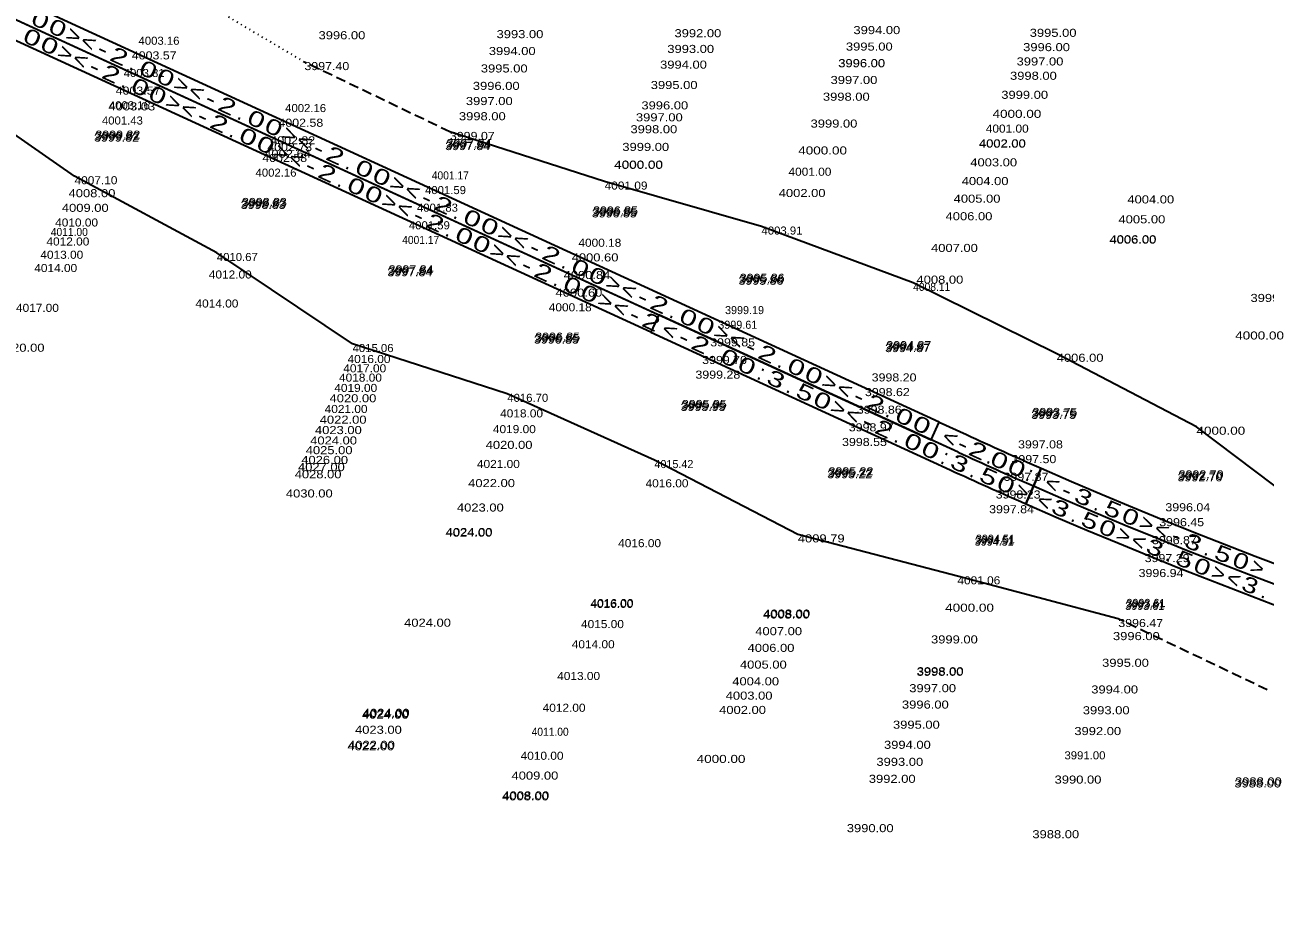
# Model space of a CAD drawing. Extents: x 49942 to 56479, y 47140 to 53283.
# Drawn here: x 50522 to 51291, y 49746 to 50295 of the extents above; entities that cross this region are included whole.
import ezdxf
from ezdxf.enums import TextEntityAlignment as Align

# ---------------------------------------------------------------- set-up
doc = ezdxf.new("R2010")
doc.units = 0
doc.header["$LTSCALE"] = 2
doc.linetypes.add('DOTTED', pattern=[1.5, 0.3, -1.2])
doc.linetypes.add('MEDIUM_DASHED', pattern=[4.5, 3, -1.5])
doc.layers.add('29', color=7, linetype='Continuous')
doc.layers.add('59', color=7, linetype='Continuous', lineweight=35)
doc.layers.add('63', color=7, linetype='Continuous', lineweight=35)

msp = doc.modelspace()

# ---------------------------------------------------------------- linework, layer by layer
at = {"layer": '59', "linetype": 'DOTTED'}
msp.add_line((50695.507, 50271.844), (50609.015, 50323.127), dxfattribs=at)
at = {"layer": '59', "linetype": 'MEDIUM_DASHED'}
for p, q in [((50785.68, 50228.581), (50695.507, 50271.844)), ((51292.327, 49882.958), (51199.974, 49926.861))]:
    msp.add_line(p, q, dxfattribs=at)
at = {"layer": '59'}
for p, q in [((50553.024, 50201.131), (50469.673, 50259.257)), ((50881.594, 50197.827), (50785.68, 50228.581)), ((50641.234, 50153.59), (50553.024, 50201.131)), ((50978.838, 50169.97), (50881.594, 50197.827)), ((51072.858, 50135.088), (50978.838, 50169.97)), ((50725.383, 50097.199), (50641.234, 50153.59)), ((51161.816, 50091.173), (51072.858, 50135.088)), ((50821.258, 50066.361), (50725.383, 50097.199)), ((51248.45, 50045.982), (51161.816, 50091.173)), ((50912.456, 50025.33), (50821.258, 50066.361)), ((51329.711, 49984.424), (51248.45, 50045.982)), ((51001.352, 49979.284), (50912.456, 50025.33)), ((51100.256, 49953.31), (51001.352, 49979.284)), ((51199.974, 49926.861), (51100.256, 49953.31))]:
    msp.add_line(p, q, dxfattribs=at)
at = {"layer": '63'}
for p, q in [((50910.165, 50104.44), (51095.828, 50019.23)), ((51088.959, 50048.79), (51105.839, 50041.043)), ((51152.244, 50020.223), (51147.426, 50009.233)), ((51147.426, 50009.233), (51152.244, 50020.223)), ((51142.608, 49998.243), (51147.426, 50009.233)), ((51147.426, 50009.233), (51142.608, 49998.243))]:
    msp.add_line(p, q, dxfattribs=at)
for points in [[(51088.959, 50048.79), (49952.321, 50570.45), (49947.316, 50559.544), (51083.954, 50037.883)], [(50910.165, 50104.44), (49942.31, 50548.638), (49947.316, 50559.544), (50915.171, 50115.346)]]:
    msp.add_lwpolyline(points, close=True, dxfattribs=at)
for points in [[(51100.834, 50030.136), (50915.171, 50115.346), (50910.165, 50104.44)], [(51100.834, 50030.136), (51083.954, 50037.883), (51088.959, 50048.79)]]:
    msp.add_lwpolyline(points, dxfattribs=at)
for radius, start, end in [(2975.18, 245.34722, 246.32672), (2987.18, 245.34722, 246.32672), (2987.18, 245.34722, 246.32672), (2975.18, 246.32672, 271.49967), (2999.18, 245.34722, 246.32672), (2987.18, 246.32672, 271.49967), (2987.18, 246.32672, 271.49967), (2999.18, 246.32672, 271.49967)]:
    msp.add_arc((52346.841, 52745.042), radius, start, end, dxfattribs=at)

# ---------------------------------------------------------------- texts
at = {"layer": '29'}
for s, width, p in [('3996.00', 1.2, (50704.276, 50285.95)), ('3993.00', 1.2, (50814.621, 50286.64)), ('3992.00', 1.2, (50924.913, 50287.213)), ('3994.00', 1.2, (51035.83, 50289.147)), ('3995.00', 1.2, (51145.084, 50287.459)), ('4003.16', 1.05, (50592.689, 50282.556)), ('3993.00', 1.2, (50920.447, 50277.481)), ('3995.00', 1.2, (51031.146, 50278.942)), ('3996.00', 1.2, (51141.013, 50278.59)), ('4003.57', 1.15, (50588.518, 50273.467)), ('3994.00', 1.2, (50809.818, 50276.175)), ('3997.00', 1.2, (51136.943, 50269.721)), ('4003.81', 1.05, (50583.512, 50262.561)), ('3997.40', 1.15, (50695.507, 50266.844)), ('3995.00', 1.2, (50804.865, 50265.383)), ('3994.00', 1.2, (50915.98, 50267.75)), ('3996.00', 1.2, (51026.397, 50268.594)), ('3996.00', 1.2, (51026.423, 50268.651)), ('3996.00', 1.2, (51026.449, 50268.708)), ('3996.00', 1.2, (50799.912, 50254.591)), ('3995.00', 1.2, (50910.187, 50255.126)), ('3997.00', 1.2, (51021.643, 50258.237)), ('3998.00', 1.2, (51132.872, 50260.852)), ('4003.57', 1.15, (50578.507, 50251.655)), ('3998.00', 1.2, (51016.89, 50247.88)), ('3999.00', 1.2, (51127.459, 50249.057)), ('4003.03', 1.2, (50574.021, 50241.88)), ('4003.16', 1.05, (50574.336, 50242.566)), ('4002.16', 1.05, (50683.574, 50240.844)), ('3997.00', 1.2, (50795.6, 50245.195)), ('3996.00', 1.2, (50904.393, 50242.503)), ('4001.43', 1.05, (50570.007, 50233.134)), ('4002.58', 1.15, (50679.403, 50231.755)), ('3998.00', 1.2, (50791.281, 50235.785)), ('3997.00', 1.2, (50901.003, 50235.115)), ('3999.00', 1.2, (51009.25, 50231.234)), ('4000.00', 1.25, (51122.046, 50237.262)), ('3999.82', 1.15, (50565.576, 50223.48)), ('3999.82', 1.15, (50565.994, 50224.389)), ('3999.07', 1.15, (50785.68, 50223.581)), ('3998.00', 1.2, (50897.612, 50227.728)), ('4001.00', 1.1, (51117.856, 50228.132)), ('3999.82', 1.15, (50565.159, 50222.571)), ('4002.73', 1.15, (50672.487, 50216.685)), ('4002.82', 1.15, (50674.398, 50220.849)), ('3997.84', 1.15, (50782.802, 50217.309)), ('3997.84', 1.15, (50783.219, 50218.218)), ('3997.84', 1.15, (50783.636, 50219.127)), ('3999.00', 1.2, (50892.588, 50216.78)), ('4002.00', 1.2, (51113.576, 50218.808)), ('4002.00', 1.2, (51113.622, 50218.907)), ('4002.00', 1.2, (51113.666, 50219.002)), ('4002.58', 1.15, (50669.392, 50209.943)), ('4002.64', 1.2, (50670.576, 50212.522)), ('4000.00', 1.25, (51001.611, 50214.588)), ('4002.16', 1.05, (50665.221, 50200.854)), ('4000.00', 1.25, (50887.482, 50205.656)), ('4000.00', 1.25, (50887.523, 50205.744)), ('4000.00', 1.25, (50887.563, 50205.832)), ('4001.00', 1.1, (50995.562, 50201.409)), ('4003.00', 1.2, (51108.255, 50207.214)), ('4007.10', 1.1, (50553.024, 50196.131)), ('4001.17', 0.95, (50774.46, 50199.132)), ('4001.09', 1.1, (50881.594, 50192.827)), ('4004.00', 1.2, (51102.934, 50195.62)), ('4008.00', 1.2, (50549.343, 50188.111)), ('4001.59', 1.05, (50770.288, 50190.044)), ('4002.00', 1.2, (50989.514, 50188.23)), ('4005.00', 1.2, (51097.936, 50184.729)), ('4004.00', 1.2, (51205.618, 50184.267)), ('4009.00', 1.2, (50545.179, 50179.036)), ('3998.83', 1.15, (50656.044, 50180.86)), ('3998.83', 1.15, (50656.462, 50181.768)), ('3998.83', 1.15, (50656.879, 50182.677)), ('4001.83', 1.05, (50765.283, 50179.137)), ('3996.85', 1.15, (50874.521, 50177.415)), ('4010.00', 1.1, (50541.014, 50169.962)), ('3996.85', 1.15, (50873.687, 50175.597)), ('3996.85', 1.15, (50874.104, 50176.506)), ('4006.00', 1.2, (51092.937, 50173.837)), ('4005.00', 1.2, (51200.108, 50171.928)), ('4011.00', 0.95, (50538.314, 50164.079)), ('4001.59', 1.05, (50760.278, 50168.231)), ('4003.91', 1.05, (50978.838, 50164.97)), ('4012.00', 1.1, (50535.614, 50158.195)), ('4001.17', 0.95, (50756.106, 50159.143)), ('4000.18', 1.1, (50865.345, 50157.42)), ('4007.00', 1.2, (51083.925, 50154.2)), ('4006.00', 1.2, (51194.48, 50159.324)), ('4006.00', 1.2, (51194.552, 50159.485)), ('4006.00', 1.2, (51194.597, 50159.588)), ('4013.00', 1.1, (50531.843, 50149.979)), ('4010.67', 1.05, (50641.234, 50148.59)), ('4000.60', 1.2, (50861.173, 50148.332)), ('4014.00', 1.1, (50528.072, 50141.763)), ('3997.84', 1.15, (50746.93, 50139.148)), ('3997.84', 1.15, (50747.347, 50140.057)), ('3997.84', 1.15, (50747.764, 50140.966)), ('4012.00', 1.1, (50636.259, 50137.75)), ('4000.84', 1.2, (50856.168, 50137.426)), ('3995.86', 1.15, (50964.572, 50133.885)), ('3995.86', 1.15, (50964.989, 50134.794)), ('3995.86', 1.15, (50965.407, 50135.703)), ('4008.00', 1.2, (51074.912, 50134.563)), ('4000.60', 1.2, (50851.163, 50126.519)), ('4008.11', 0.95, (51072.858, 50130.088)), ('3999.00', 1.2, (51281.921, 50123.228)), ('4017.00', 1.1, (50516.743, 50117.077)), ('4014.00', 1.1, (50628.01, 50119.776)), ('4000.18', 1.1, (50846.991, 50117.431)), ('4000.00', 1.25, (51272.46, 50099.981)), ('4020.00', 1.2, (50505.413, 50092.391)), ('4015.06', 1.05, (50725.383, 50092.2)), ('3996.85', 1.15, (50837.815, 50097.436)), ('3996.85', 1.15, (50838.232, 50098.345)), ('3996.85', 1.15, (50838.649, 50099.254)), ('3999.85', 1.15, (50947.053, 50095.714)), ('3994.87', 1.15, (51055.457, 50092.174)), ('3994.87', 1.15, (51055.875, 50093.083)), ('3994.87', 1.15, (51056.292, 50093.991)), ('4016.00', 1.1, (50722.263, 50085.401)), ('3999.70', 1.15, (50942.048, 50084.808)), ('4006.00', 1.2, (51161.816, 50086.173)), ('4017.00', 1.1, (50719.617, 50079.637)), ('4018.00', 1.1, (50716.971, 50073.872)), ('3999.28', 1.15, (50937.877, 50075.719)), ('3998.20', 1.15, (51047.115, 50073.997)), ('4019.00', 1.1, (50714.037, 50067.479)), ('4016.70', 1.05, (50821.258, 50061.361)), ('3998.62', 1.15, (51042.944, 50064.908)), ('4021.00', 1.1, (50708.059, 50054.453)), ('4020.00', 1.2, (50711.103, 50061.085)), ('3995.95', 1.15, (50928.7, 50055.724)), ('3995.95', 1.15, (50929.117, 50056.633)), ('3995.95', 1.15, (50929.534, 50057.542)), ('3998.86', 1.15, (51037.938, 50054.002)), ('4022.00', 1.2, (50705.015, 50047.821)), ('4018.00', 1.1, (50816.83, 50051.713)), ('3993.75', 1.15, (51146.014, 50050.785)), ('3993.75', 1.15, (51146.422, 50051.698)), ('3993.75', 1.15, (51146.829, 50052.611)), ('4023.00', 1.2, (50702.062, 50041.387)), ('4019.00', 1.1, (50812.355, 50041.961)), ('3998.97', 1.15, (51032.933, 50043.096)), ('4000.00', 1.25, (51248.45, 50040.982)), ('4024.00', 1.2, (50699.109, 50034.953)), ('4020.00', 1.2, (50807.879, 50032.21)), ('3998.55', 1.15, (51028.762, 50034.007)), ('3997.08', 1.15, (51137.859, 50032.523)), ('4026.00', 1.2, (50693.569, 50022.881)), ('4025.00', 1.2, (50696.339, 50028.917)), ('3997.50', 1.15, (51133.782, 50023.392)), ('4027.00', 1.2, (50691.531, 50018.441)), ('4021.00', 1.1, (50802.449, 50020.378)), ('3995.22', 1.15, (51020.42, 50015.83)), ('4028.00', 1.2, (50689.493, 50014.001)), ('4022.00', 1.2, (50797.019, 50008.547)), ('4016.00', 1.1, (50906.983, 50008.405)), ('3995.22', 1.15, (51019.585, 50014.012)), ('3995.22', 1.15, (51020.002, 50014.921)), ('3997.87', 1.15, (51128.889, 50012.435)), ('3992.70', 1.15, (51236.697, 50012.1)), ('3992.70', 1.15, (51237.074, 50013.026)), ('3992.70', 1.15, (51237.45, 50013.952)), ('4030.00', 1.2, (50684.041, 50002.12)), ('3998.23', 1.15, (51123.997, 50001.477)), ('4023.00', 1.2, (50790.065, 49993.394)), ('3997.84', 1.15, (51119.919, 49992.346)), ('3996.04', 1.15, (51229.158, 49993.575)), ('4024.00', 1.2, (50782.932, 49977.853)), ('4024.00', 1.2, (50783.021, 49978.048)), ('4024.00', 1.2, (50783.111, 49978.242)), ('3996.45', 1.15, (51225.389, 49984.313)), ('4016.00', 1.1, (50889.971, 49971.339)), ('4009.79', 1.2, (51001.352, 49974.284)), ('3996.87', 1.15, (51220.865, 49973.198)), ('3997.29', 1.15, (51216.342, 49962.083)), ('4001.06', 1.1, (51100.256, 49948.31)), ('3996.94', 1.15, (51212.573, 49952.821)), ('4016.00', 1.1, (50872.697, 49933.7)), ('4016.00', 1.1, (50872.814, 49933.956)), ('4016.00', 1.1, (50872.932, 49934.211)), ('4000.00', 1.25, (51092.688, 49931.362)), ('4008.00', 1.2, (50979.708, 49927.124)), ('4008.00', 1.2, (50979.843, 49927.419)), ('4008.00', 1.2, (50979.979, 49927.714)), ('4024.00', 1.2, (50757.323, 49922.053)), ('4015.00', 1.1, (50866.963, 49921.207)), ('4007.00', 1.2, (50974.965, 49916.791)), ('3996.47', 1.15, (51199.974, 49921.862)), ('4014.00', 1.1, (50861.229, 49908.713)), ('3999.00', 1.2, (51083.908, 49911.698)), ('3996.00', 1.2, (51196.677, 49913.761)), ('4006.00', 1.2, (50970.223, 49906.458)), ('4005.00', 1.2, (50965.471, 49896.104)), ('3995.00', 1.2, (51189.95, 49897.231)), ('4013.00', 1.1, (50852.201, 49889.041)), ('4004.00', 1.2, (50960.72, 49885.751)), ('3998.00', 1.2, (51074.957, 49891.652)), ('3998.00', 1.2, (51075.034, 49891.824)), ('3998.00', 1.2, (51075.111, 49891.996)), ('4003.00', 1.2, (50956.65, 49876.883)), ('3997.00', 1.2, (51070.422, 49881.497)), ('3994.00', 1.2, (51183.224, 49880.701)), ('4012.00', 1.1, (50843.172, 49869.369)), ('3996.00', 1.2, (51065.888, 49871.342)), ('4024.00', 1.2, (50731.175, 49865.079)), ('4024.00', 1.2, (50731.444, 49865.666)), ('4024.00', 1.2, (50731.714, 49866.253)), ('4002.00', 1.2, (50952.58, 49868.016)), ('3993.00', 1.2, (51177.981, 49867.818)), ('4023.00', 1.2, (50726.887, 49855.737)), ('4011.00', 0.95, (50836.351, 49854.507)), ('3995.00', 1.2, (51060.325, 49858.885)), ('3992.00', 1.2, (51172.738, 49854.935)), ('4022.00', 1.2, (50722.599, 49846.393)), ('3994.00', 1.2, (51054.763, 49846.427)), ('4022.00', 1.2, (50722.188, 49845.499)), ('4010.00', 1.1, (50829.531, 49839.646)), ('3991.00', 1.05, (51166.624, 49839.911)), ('4000.00', 1.25, (50938.656, 49837.678)), ('3993.00', 1.2, (51050.056, 49835.886)), ('4009.00', 1.2, (50823.892, 49827.36)), ('3992.00', 1.2, (51045.348, 49825.344)), ('3990.00', 1.2, (51160.509, 49824.886)), ('3988.00', 1.2, (51272.345, 49823.726)), ('3988.00', 1.2, (51271.892, 49822.495)), ('4008.00', 1.2, (50817.982, 49814.482)), ('4008.00', 1.2, (50818.253, 49815.074)), ('3990.00', 1.2, (51031.709, 49794.798)), ('3988.00', 1.2, (51146.733, 49791.033))]:
    msp.add_text(s, height=5, dxfattribs=dict(at, width=width)).set_placement(p)
for s, p in [('3999.19', (50956.23, 50115.709)), ('3999.61', (50952.059, 50106.62)), ('4015.42', (50912.456, 50020.33)), ('3994.51', (51110.95, 49972.258)), ('3994.51', (51111.357, 49973.171)), ('3994.51', (51111.765, 49974.084)), ('3993.61', (51204.28, 49932.443)), ('3993.61', (51204.657, 49933.37)), ('3993.61', (51205.034, 49934.296))]:
    msp.add_text(s, height=5, dxfattribs=at).set_placement(p)
at = {"layer": '63'}
for s, rotation, width, p in [('0', 335.347, 1.45, (50529.86, 50293.506)), ('0', 335.347, 1.45, (50540.623, 50288.566)), ('0', 335.347, 1.45, (50524.854, 50282.599)), ('>', 335.347, 1.2, (50550.57, 50284)), ('0', 335.347, 1.45, (50535.617, 50277.659)), ('>', 335.347, 1.2, (50545.564, 50273.094)), ('<', 335.347, 1.2, (50559.701, 50279.81)), ('<', 335.347, 1.2, (50554.696, 50268.903)), ('-', 335.347, 1.4, (50568.833, 50275.619)), ('2', 335.347, 1.45, (50578.78, 50271.053)), ('-', 335.347, 1.4, (50563.827, 50264.712)), ('2', 335.347, 1.45, (50573.775, 50260.147)), ('0', 335.347, 1.45, (50596.814, 50262.777)), ('0', 335.347, 1.45, (50607.577, 50257.837)), ('0', 335.347, 1.45, (50591.809, 50251.87)), ('>', 335.347, 1.2, (50617.524, 50253.272)), ('0', 335.347, 1.45, (50602.572, 50246.931)), ('>', 335.347, 1.2, (50612.519, 50242.365)), ('<', 335.347, 1.2, (50626.656, 50249.081)), ('<', 335.347, 1.2, (50621.65, 50238.175)), ('-', 335.347, 1.4, (50635.787, 50244.89)), ('2', 335.347, 1.45, (50645.735, 50240.325)), ('-', 335.347, 1.4, (50630.782, 50233.984)), ('2', 335.347, 1.45, (50640.729, 50229.418)), ('0', 335.347, 1.45, (50663.769, 50232.048)), ('0', 335.347, 1.45, (50674.532, 50227.108)), ('0', 335.347, 1.45, (50658.763, 50221.142)), ('>', 335.347, 1.2, (50684.479, 50222.543)), ('0', 335.347, 1.45, (50669.526, 50216.202)), ('>', 335.347, 1.2, (50679.473, 50211.637)), ('<', 335.347, 1.2, (50693.61, 50218.352)), ('<', 335.347, 1.2, (50688.605, 50207.446)), ('-', 335.347, 1.4, (50702.742, 50214.161)), ('2', 335.347, 1.45, (50712.689, 50209.596)), ('-', 335.347, 1.4, (50697.736, 50203.255)), ('2', 335.347, 1.45, (50707.684, 50198.689)), ('0', 335.347, 1.45, (50730.723, 50201.319)), ('0', 335.347, 1.45, (50741.486, 50196.379)), ('0', 335.347, 1.45, (50725.718, 50190.413)), ('>', 335.347, 1.2, (50751.433, 50191.814)), ('0', 335.347, 1.45, (50736.481, 50185.473)), ('>', 335.347, 1.2, (50746.428, 50180.908)), ('<', 335.347, 1.2, (50760.565, 50187.623)), ('<', 335.347, 1.2, (50755.559, 50176.717)), ('-', 335.347, 1.4, (50769.696, 50183.432)), ('2', 335.347, 1.45, (50779.644, 50178.867)), ('-', 335.347, 1.4, (50764.691, 50172.526)), ('2', 335.347, 1.45, (50774.638, 50167.961)), ('0', 335.347, 1.45, (50797.678, 50170.59)), ('0', 335.347, 1.45, (50808.441, 50165.651)), ('0', 335.347, 1.45, (50792.672, 50159.684)), ('>', 335.347, 1.2, (50818.388, 50161.085)), ('0', 335.347, 1.45, (50803.435, 50154.744)), ('>', 335.347, 1.2, (50813.382, 50150.179)), ('<', 335.347, 1.2, (50827.519, 50156.894)), ('<', 335.347, 1.2, (50822.514, 50145.988)), ('-', 335.347, 1.4, (50836.651, 50152.704)), ('2', 335.347, 1.45, (50846.598, 50148.138)), ('-', 335.347, 1.4, (50831.645, 50141.797)), ('2', 335.347, 1.45, (50841.593, 50137.232)), ('0', 335.347, 1.45, (50864.632, 50139.862)), ('0', 335.347, 1.45, (50875.395, 50134.922)), ('0', 335.347, 1.45, (50859.627, 50128.955)), ('>', 335.347, 1.2, (50885.342, 50130.356)), ('0', 335.347, 1.45, (50870.39, 50124.015)), ('>', 335.347, 1.2, (50880.337, 50119.45)), ('<', 335.347, 1.2, (50894.474, 50126.166)), ('<', 335.347, 1.2, (50889.468, 50115.259)), ('-', 335.347, 1.4, (50903.605, 50121.975)), ('2', 335.347, 1.45, (50913.553, 50117.409)), ('-', 335.347, 1.4, (50898.6, 50111.068)), ('2', 335.347, 1.45, (50908.547, 50106.503)), ('0', 335.347, 1.45, (50931.587, 50109.133)), ('0', 335.347, 1.45, (50942.35, 50104.193)), ('<', 335.347, 1.2, (50919.96, 50101.265)), ('>', 335.347, 1.2, (50952.297, 50099.628)), ('-', 335.347, 1.4, (50929.092, 50097.074)), ('2', 335.347, 1.45, (50939.039, 50092.509)), ('<', 335.347, 1.2, (50961.428, 50095.437)), ('0', 335.347, 1.45, (50957.073, 50084.232)), ('-', 335.347, 1.4, (50970.56, 50091.246)), ('2', 335.347, 1.45, (50980.507, 50086.681)), ('0', 335.347, 1.45, (50967.836, 50079.293)), ('0', 335.347, 1.45, (50998.541, 50078.404)), ('0', 335.347, 1.45, (51009.304, 50073.464)), ('3', 335.347, 1.45, (50985.87, 50071.016)), ('>', 335.347, 1.2, (51019.251, 50068.899)), ('5', 335.347, 1.45, (51003.904, 50062.739)), ('0', 335.347, 1.45, (51014.667, 50057.799)), ('<', 335.347, 1.2, (51028.383, 50064.708)), ('>', 335.347, 1.2, (51024.614, 50053.234)), ('-', 335.347, 1.4, (51037.514, 50060.517)), ('2', 335.347, 1.45, (51047.462, 50055.952)), ('<', 335.347, 1.2, (51033.746, 50049.043)), ('0', 335.347, 1.45, (51065.496, 50047.675)), ('0', 335.347, 1.45, (51076.259, 50042.735)), ('-', 335.347, 1.4, (51042.877, 50044.852)), ('2', 335.347, 1.45, (51052.825, 50040.287)), ('0', 335.347, 1.45, (51070.859, 50032.01)), ('0', 335.347, 1.45, (51081.622, 50027.071)), ('<', 335.347, 1.2, (51093.749, 50034.708)), ('-', 335.362, 1.4, (51101.994, 50030.925)), ('2', 335.511, 1.45, (51111.074, 50026.78)), ('3', 335.399, 1.45, (51099.652, 50018.801)), ('0', 335.792, 1.45, (51124.401, 50020.76)), ('5', 335.754, 1.45, (51117.683, 50010.623)), ('0', 336.018, 1.45, (51135.162, 50015.958)), ('0', 335.98, 1.45, (51128.469, 50005.8)), ('<', 336.481, 1.15, (51157.203, 50006.276)), ('>', 336.189, 1.15, (51138.454, 50001.38)), ('-', 336.675, 1.35, (51166.441, 50002.282)), ('3', 336.886, 1.45, (51176.52, 49997.968)), ('<', 336.48, 1.15, (51152.356, 49995.299)), ('3', 336.689, 1.45, (51162.379, 49990.968)), ('5', 337.268, 1.4, (51194.833, 49990.238)), ('5', 337.068, 1.4, (51180.592, 49983.206)), ('0', 337.496, 1.4, (51205.786, 49985.683)), ('>', 337.706, 1.15, (51215.926, 49981.511)), ('0', 337.294, 1.4, (51191.485, 49978.631)), ('>', 337.503, 1.15, (51201.569, 49974.44)), ('<', 337.9, 1.15, (51225.247, 49977.715)), ('<', 337.695, 1.15, (51210.84, 49970.626)), ('3', 337.905, 1.4, (51220.953, 49966.508)), ('-', 338.093, 1.3, (51234.581, 49973.95)), ('3', 338.304, 1.4, (51244.764, 49969.886)), ('5', 338.284, 1.4, (51239.326, 49959.134)), ('5', 338.686, 1.4, (51263.262, 49962.611)), ('0', 338.914, 1.35, (51274.326, 49958.327)), ('0', 338.51, 1.4, (51250.315, 49954.79)), ('>', 338.719, 1.1, (51260.485, 49950.813)), ('>', 339.125, 1.1, (51284.565, 49954.407)), ('<', 338.911, 1.1, (51269.835, 49947.197)), ('3', 339.12, 1.35, (51280.034, 49943.293))]:
    msp.add_text(s, height=9.6, rotation=rotation, dxfattribs=dict(at, width=width)).set_placement(p, align=Align.CENTER)
for s, rotation, p in [('.', 335.347, (50587.797, 50266.915)), ('.', 335.347, (50582.792, 50256.009)), ('.', 335.347, (50654.752, 50236.186)), ('.', 335.347, (50649.746, 50225.28)), ('.', 335.347, (50721.706, 50205.458)), ('.', 335.347, (50716.701, 50194.551)), ('.', 335.347, (50788.661, 50174.729)), ('.', 335.347, (50783.655, 50163.822)), ('.', 335.347, (50855.615, 50144)), ('.', 335.347, (50850.61, 50133.094)), ('.', 335.347, (50922.57, 50113.271)), ('.', 335.347, (50948.056, 50088.371)), (':', 335.347, (50976.853, 50075.154)), ('.', 335.347, (50989.524, 50082.542)), ('.', 335.347, (50994.887, 50066.878)), ('.', 335.347, (51056.479, 50051.814)), ('.', 335.347, (51061.842, 50036.149)), (':', 335.347, (51090.639, 50022.932)), ('.', 335.68, (51119.092, 50023.146)), ('.', 335.565, (51108.661, 50014.694)), (':', 336.188, (51143.211, 50012.395)), ('.', 337.077, (51185.669, 49994.086)), ('.', 336.879, (51171.478, 49987.07)), ('.', 338.495, (51254.006, 49966.231)), ('.', 338.094, (51230.133, 49962.804)), ('.', 339.309, (51289.29, 49939.784))]:
    msp.add_text(s, height=9.6, rotation=rotation, dxfattribs=at).set_placement(p, align=Align.CENTER)

doc.saveas('drawing.dxf')
